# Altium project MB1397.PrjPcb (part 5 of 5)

## Sheet USB-TYPEC_CON.SchDoc: USB-TYPEC_CON
size A4; Date: Not used; ApprovedBy: Not used; CheckedBy: Not used; Author: Not used; CompanyName: STMicroelectronics; DrawnBy: Not used; Engineer: Not used; Organization: Not used; Address1: Not used; Address2: Not used; Address3: Not used; Address4: Not used; DocumentNumber: Not used; Revision: Not used; SheetNumber: 6; SheetTotal: 22
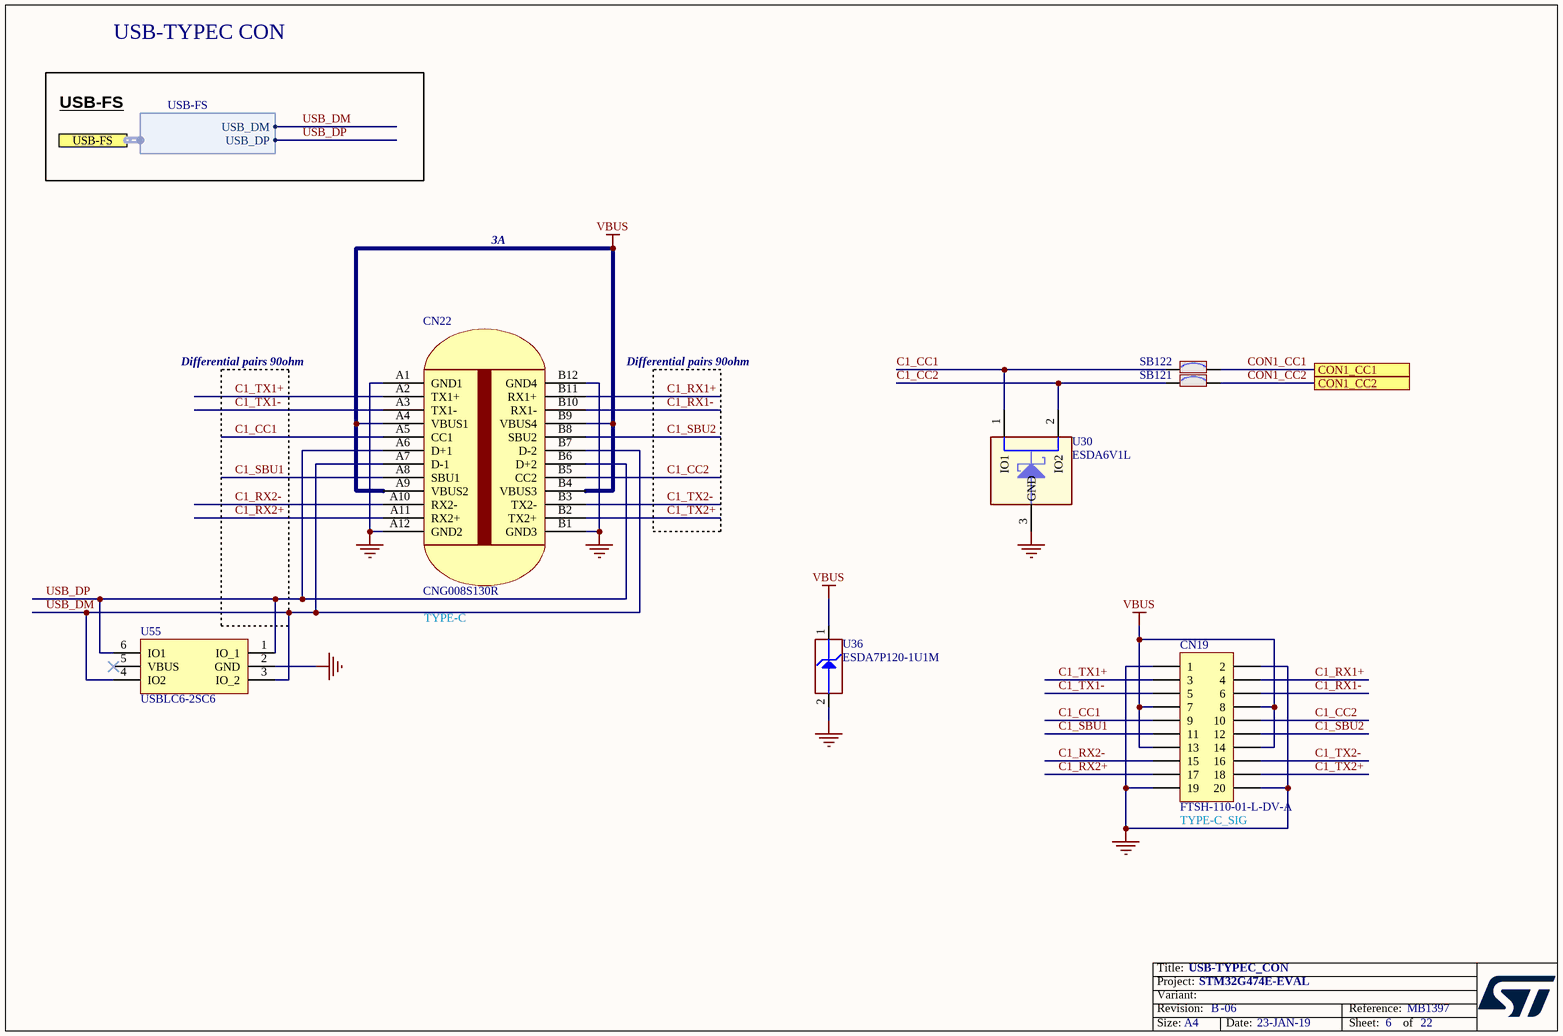
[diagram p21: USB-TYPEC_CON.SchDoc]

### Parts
CN19  value FTSH-110-01-L-DV-A  [CON_SAMTEC_FTSH-110-01-L-DV-A]  (hidden comment: Header 10x2)
CN22  value CNG008S130R  [CON_USB-TYPEC_LITKCONN-TECHNOLOGY_CNG008S130R]  (hidden comment: USB Type-C)
SB121  SB_ON  [SOLDER-BRIDGE_R0603-0R]  (value not drawn)
SB122  SB_ON  [SOLDER-BRIDGE_R0603-0R]  (value not drawn)
U30  value ESDA6V1L  [ESD_SOT23]  (hidden comment: ESDAxxL)
U36  value ESDA7P120-1U1M  [ESD_QFN1610_2N_1K_2A]  (hidden comment: ESD-TRANSIL)
U55  USBLC6-2SC6  [ESD_SOT23-6L]

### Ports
CON1_CC1, CON1_CC2, USB-FS (harness USB-FS)

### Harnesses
USB-FS: USB_DM, USB_DP

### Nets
GND: CN19.1 CN19.2 CN19.19 CN19.20 CN22.A1(GND1) CN22.A12(GND2) CN22.B1(GND3) CN22.B12(GND4) U30.3(GND) U36.2(GND) U55.2(GND)
VBUS: CN19.7 CN19.8 CN19.13 CN19.14 CN22.A4(VBUS1) CN22.A9(VBUS2) CN22.B4(VBUS3) CN22.B9(VBUS4) U36.1(IO1)
C1_CC1: CN19.9 CN22.A5(CC1) SB122.1 U30.1(IO1)
C1_CC2: CN19.10 CN22.B5(CC2) SB121.1 U30.2(IO2)
C1_RX1+: CN19.4 CN22.B11(RX1+)
C1_RX1-: CN19.6 CN22.B10(RX1-)
C1_RX2+: CN19.17 CN22.A11(RX2+)
C1_RX2-: CN19.15 CN22.A10(RX2-)
C1_SBU1: CN19.11 CN22.A8(SBU1)
C1_SBU2: CN19.12 CN22.B8(SBU2)
C1_TX1+: CN19.3 CN22.A2(TX1+)
C1_TX1-: CN19.5 CN22.A3(TX1-)
C1_TX2+: CN19.18 CN22.B2(TX2+)
C1_TX2-: CN19.16 CN22.B3(TX2-)
CON1_CC1: SB122.2 ; port CON1_CC1
CON1_CC2: SB121.2 ; port CON1_CC2
USB_DM: CN22.A7(D-1) CN22.B7(D-2) U55.3(IO_2) U55.4(IO2) ; port USB-FS.USB_DM
USB_DP: CN22.A6(D+1) CN22.B6(D+2) U55.1(IO_1) U55.6(IO1) ; port USB-FS.USB_DP

Not connected (* = marked no-connect by the designer): U55 5(VBUS)*

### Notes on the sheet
- USB-TYPEC CON
- USB-FS
- 3A
- Differential pairs 90ohm
- TYPE-C
- (near CN19) TYPE-C_SIG

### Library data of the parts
CN19 = MCD-01561: Header 10x2, 1.27mm, VR, CMS, Height 3.05mm with alignment pin; Part_Type: Connector; Manufacturer: SAMTEC; Provided_By: SUBCO; Initial_Board_Reference: MB1397; Path: ws/MCD_ApplicationBoards/Lists/MCDPARTSdatabase; Item Type: Item; Remark: new part FTSH-110-01-L-DV-A to replace MCD-00557 footprint
CN22 = MCD-00678: USB Type C certified Connector SMT Mid-mount; Manufacturer: LITKCON TECHNOLOGY; Provided_By: SUBCO; Initial_Board_Reference: MB1272; Path: ws/MCD_ApplicationBoards/Lists/MCDPARTSdatabase; Item Type: Item
SB121 SB122 = MCD-00071: Solder Bridge ON; Part_Type: Mechanical; Manufacturer_Part_Number: RC0603JR-070RL; Manufacturer: YAGEO; Provided_By: SUBCO; Initial_Board_Reference: MB1274; Path: ws/MCD_ApplicationBoards/Lists/MCDPARTSdatabase; Item Type: Item
U30 = MCD-00255: Dual Transil array ESD protection; Part_Type: Diode; Manufacturer: STMICROELECTRONICS; BMS_Part_Number: 9179033; Provided_By: SUBCO with ST control; Initial_Board_Reference: MB1311; Path: ws/MCD_ApplicationBoards/Lists/MCDPARTSdatabase; Item Type: Item
U36 = MCD-01026: High power transient voltage suppressor; Part_Type: Diode; Manufacturer: STMICROELECTRONICS; BMS_Part_Number: 9179046; Provided_By: SUBCO with ST control; Initial_Board_Reference: MB1378; Remark: Footprint moved fromROU lib: DFN105P160X60-2N to global-lib: ESD_QFN1610_2N_1K_2A; Path: ws/MCD_ApplicationBoards/Lists/MCDPARTSdatabase; Item Type: Item
U55 = MCD-00163: Very low capacitance ESD protection; Part_Type: IC; Manufacturer: STMICROELECTRONICS; BMS_Part_Number: 9151075; Provided_By: SUBCO with ST control; Initial_Board_Reference: MB1263; Path: ws/MCD_ApplicationBoards/Lists/MCDPARTSdatabase; Item Type: Item

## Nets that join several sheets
1V8: Audio (6 pins), Power_Board (SB42.2 TP4.1)
3V3: Audio (5 pins), LCD&SDcard (12 pins), MotorControl (10 pins), STM32_microcontroller_power (JP6.3 JP11.1), Power_Board (5 pins), Analog_Interfaces (R111.2), Peripherals (LD1.1 LD2.1 LD3.1 LD4.1), RS232&RS485 (7 pins)
5V: FDCAN (C44.1 C53.1 U10.3 U15.3), LCD&SDcard (SB46.1), MotorControl (CN2.25 CN4.25), SmartCard (C152.1 C153.2 U42.6), Power_Board (11 pins), Analog_Interfaces (C159.2 Q4.3 R318.2 U4.8), Multi-Function_Expander (R241.2 T8.4), Peripherals (SB1.2 SB34.2), STLink_V3E_SWD (R277.2), ExtensionConnector (CN5.60 CN6.60)
5V_D: Power_Board (JP12.5), STLink_V3E_SWD (D4.1), ExtensionConnector (CN5.49 CN6.49)
5V_EXT: Power_Board (8 pins), STLink_V3E_SWD (D3.1), USB_PD (5 pins)
5V_STLK: Power_Board (JP12.1), STLink_V3E_SWD (SB41.2)
5V_USB_CHGR: Power_Board (JP12.9), STLink_V3E_SWD (8 pins)
5V_USB_PD: Power_Board (JP12.3), STLink_V3E_SWD (D5.1), USB_PD (D8.2 D9.2)
AGND: STM32_microcontroller_power (10 pins), Analog_Interfaces (35 pins)
GND: FMC_Memory (7 pins), Audio (33 pins), QSPI_Memory (C51.1 C184.1 U12.10 U54.10), FDCAN (10 pins), LCD&SDcard (23 pins), MotorControl (49 pins), SmartCard (15 pins), STM32_microcontroller_power (33 pins), Power_Board (31 pins), HW_Mechanical_Parts (H1.1 H2.1 H5.1 H6.1), Analog_Interfaces (5 pins), Multi-Function_Expander (26 pins), Peripherals (17 pins), STLink_V3E_SWD (97 pins), ExtensionConnector (7 pins), USB_PD (10 pins), Debug_connector (26 pins), RS232&RS485 (14 pins), USB-TYPEC_CON (11 pins)
VBUS: USB_PD (10 pins), USB-TYPEC_CON (9 pins)
VDD: STM32_microcontroller_IOs (R73.2 R80.2), FMC_Memory (7 pins), Audio (5 pins), QSPI_Memory (6 pins), FDCAN (C40.1 C52.1 U10.5 U15.5), LCD&SDcard (8 pins), SmartCard (8 pins), STM32_microcontroller_power (JP7.1 JP11.2 SW7.2), Analog_Interfaces (C50.1 R158.2 R179.2 RV2.1), Multi-Function_Expander (11 pins), Peripherals (6 pins), STLink_V3E_SWD (CN16.3 R282.2), ExtensionConnector (CN5.48 CN6.48), Debug_connector (9 pins), RS232&RS485 (5 pins)
VDD_ADJ: STM32_microcontroller_power (JP11.3), Power_Board (SB48.2)
VDD_MCU: STM32_microcontroller_power (18 pins), Multi-Function_Expander (JP13.2 SB43.2)
VREF_EXT: STM32_microcontroller_power (SB84.1), Analog_Interfaces (5 pins)
A0: STM32_microcontroller_IOs (R136.2), FMC_Memory (U11.A3), ExtensionConnector (CN6.51)
A1: STM32_microcontroller_IOs (R138.2), FMC_Memory (U11.A4), ExtensionConnector (CN6.54)
A2: STM32_microcontroller_IOs (R132.2), FMC_Memory (U11.A5), ExtensionConnector (CN6.46)
A3: STM32_microcontroller_IOs (R139.2), FMC_Memory (U11.B3), ExtensionConnector (CN6.58)
A4: STM32_microcontroller_IOs (R140.2), FMC_Memory (U11.B4), ExtensionConnector (CN6.57)
A5: STM32_microcontroller_IOs (R137.2), FMC_Memory (U11.C3), ExtensionConnector (CN6.53)
A6: STM32_microcontroller_IOs (R93.2), FMC_Memory (U11.C4), ExtensionConnector (CN6.30)
A7: STM32_microcontroller_IOs (R89.2), FMC_Memory (U11.D4), ExtensionConnector (CN6.29)
A8: STM32_microcontroller_IOs (R88.2), FMC_Memory (U11.H2), ExtensionConnector (CN6.28)
A9: STM32_microcontroller_IOs (R87.2), FMC_Memory (U11.H3), ExtensionConnector (CN6.26)
A10: STM32_microcontroller_IOs (R48.2), FMC_Memory (U11.H4), ExtensionConnector (CN5.22)
A11: STM32_microcontroller_IOs (R28.2), FMC_Memory (U11.H5), ExtensionConnector (CN5.21)
A12: STM32_microcontroller_IOs (R50.2), FMC_Memory (U11.G3), ExtensionConnector (CN5.18)
A13: STM32_microcontroller_IOs (R27.2), FMC_Memory (U11.G4), ExtensionConnector (CN5.19)
A14: STM32_microcontroller_IOs (R53.2), FMC_Memory (U11.F3), ExtensionConnector (CN5.17)
A15: STM32_microcontroller_IOs (R68.2), FMC_Memory (U11.F4), ExtensionConnector (CN5.16)
A16: STM32_microcontroller_IOs (R39.2), FMC_Memory (U11.E4), ExtensionConnector (CN6.7)
A17: STM32_microcontroller_IOs (R42.2), FMC_Memory (U11.D3), ExtensionConnector (CN6.6)
A18: STM32_microcontroller_IOs (R41.2), FMC_Memory (U11.H1), ExtensionConnector (CN6.5)
A19: STM32_microcontroller_IOs (R146.1), FMC_Memory (R156.2 U11.G2), ExtensionConnector (CN5.54)
A20: STM32_microcontroller_IOs (R143.1), FMC_Memory (R162.2 U11.H6), ExtensionConnector (CN5.56)
ADC_OUTN: STM32_microcontroller_IOs (SB27.1), Analog_Interfaces (C35.1 R152.2)
Audio_INT: STM32_microcontroller_IOs (R43.2), Audio (U35.G3)
BK_Drive: STM32_microcontroller_IOs (R26.1), Peripherals (R175.1)
BOOT0: STM32_microcontroller_IOs (R123.1), STM32_microcontroller_power (JP8.2 R182.1)
CON1_CC1: STM32_microcontroller_IOs (SB21.2), USB_PD (JP15.3), USB-TYPEC_CON (SB122.2)
CON1_CC2: STM32_microcontroller_IOs (SB96.2), USB_PD (JP14.3), USB-TYPEC_CON (SB121.2)
D0: STM32_microcontroller_IOs (R29.2), FMC_Memory (U11.B6), ExtensionConnector (CN6.4)
D1: STM32_microcontroller_IOs (R40.2), FMC_Memory (U11.C5), ExtensionConnector (CN6.3)
D2: STM32_microcontroller_IOs (R83.2), FMC_Memory (U11.C6), ExtensionConnector (CN5.27)
D3: STM32_microcontroller_IOs (R85.2), FMC_Memory (U11.D5), ExtensionConnector (CN5.28)
D4: STM32_microcontroller_IOs (R84.1), FMC_Memory (U11.E5), ExtensionConnector (CN6.27)
D5: STM32_microcontroller_IOs (R82.1), FMC_Memory (U11.F5), ExtensionConnector (CN6.25)
D6: STM32_microcontroller_IOs (R79.1), FMC_Memory (U11.F6), ExtensionConnector (CN6.24)
D7: STM32_microcontroller_IOs (R75.1), FMC_Memory (U11.G6), ExtensionConnector (CN6.23)
D8: STM32_microcontroller_IOs (R71.1), FMC_Memory (U11.B1), ExtensionConnector (CN6.22)
D9: STM32_microcontroller_IOs (R69.1), FMC_Memory (U11.C1), ExtensionConnector (CN6.21)
D10: STM32_microcontroller_IOs (R63.1), FMC_Memory (U11.C2), ExtensionConnector (CN6.20)
D11: STM32_microcontroller_IOs (R62.1), FMC_Memory (U11.D2), ExtensionConnector (CN6.19)
D12: STM32_microcontroller_IOs (R60.1), FMC_Memory (U11.E2), ExtensionConnector (CN6.18)
D13: STM32_microcontroller_IOs (R34.2), FMC_Memory (U11.F2), ExtensionConnector (CN6.12)
D14: STM32_microcontroller_IOs (R37.2), FMC_Memory (U11.F1), ExtensionConnector (CN6.9)
D15: STM32_microcontroller_IOs (R38.2), FMC_Memory (U11.G1), ExtensionConnector (CN6.8)
DAC: STM32_microcontroller_IOs (SB25.1), Analog_Interfaces (R153.2)
DISCHARGE: STM32_microcontroller_IOs (SB18.2), USB_PD (SB44.1)
FDCAN1_RX: STM32_microcontroller_IOs (JP1.2), FDCAN (U15.4)
FDCAN1_TX: STM32_microcontroller_IOs (R127.2), FDCAN (U15.1)
FDCAN2_RX: STM32_microcontroller_IOs (R112.2), FDCAN (U10.4)
FDCAN2_TX: STM32_microcontroller_IOs (SB5.2), FDCAN (U10.1)
FMC_NBL0: STM32_microcontroller_IOs (R148.1), FMC_Memory (U11.A1), ExtensionConnector (CN5.55)
FMC_NBL1: STM32_microcontroller_IOs (R149.1), FMC_Memory (U11.B2), ExtensionConnector (CN5.53)
FMC_NE1: STM32_microcontroller_IOs (R101.2), FMC_Memory (R171.1 U11.B5), ExtensionConnector (CN5.40)
FMC_NOE: STM32_microcontroller_IOs (R94.2), FMC_Memory (U11.A2), ExtensionConnector (CN5.33)
FMC_NWE: STM32_microcontroller_IOs (R97.2), FMC_Memory (U11.G5), ExtensionConnector (CN5.38)
I2C3_SCL: STM32_microcontroller_IOs (R73.1 R74.2), Multi-Function_Expander (R243.1), Peripherals (CN1.3 R17.1 U1.1 U1.6)
I2C3_SDA: STM32_microcontroller_IOs (R78.2 R80.1), Multi-Function_Expander (R239.1), Peripherals (CN1.1 R13.1 U1.3 U1.4)
I2C3_SMBA: STM32_microcontroller_IOs (R70.2), Peripherals (R15.1 R16.1)
JTCK-SWCLK: STM32_microcontroller_IOs (R47.1), STLink_V3E_SWD (CN29.1 R206.2 U40.M11), Debug_connector (R193.2)
JTDI: STM32_microcontroller_IOs (R54.1), STLink_V3E_SWD (R199.2), Debug_connector (R185.2)
JTDO-SWO: STM32_microcontroller_IOs (R107.2), STLink_V3E_SWD (R204.2 U40.D12), Debug_connector (R209.2)
JTMS-SWDIO: STM32_microcontroller_IOs (R44.1), STLink_V3E_SWD (CN29.2 R208.2 R285.2 U40.L2), Debug_connector (R188.2)
JTRST: STM32_microcontroller_IOs (R109.1), Debug_connector (R205.2)
LCD_CS: STM32_microcontroller_IOs (R49.1), LCD&SDcard (R216.1)
LED1: STM32_microcontroller_IOs (R81.2), Peripherals (R297.2)
LED3: STM32_microcontroller_IOs (R96.2), Peripherals (R299.2)
MC1_Ain: STM32_microcontroller_IOs (SB113.1), MotorControl (R64.2)
MC1_Bin: STM32_microcontroller_IOs (SB114.1), MotorControl (R55.2)
MC1_BusVoltage: STM32_microcontroller_IOs (SB115.1), MotorControl (C4.1 R3.2)
MC1_Cin: STM32_microcontroller_IOs (SB99.1), MotorControl (R52.2)
MC1_DissipativeBrake: STM32_microcontroller_IOs (SB97.1), MotorControl (CN2.23)
MC1_EnA: STM32_microcontroller_IOs (SB98.1), MotorControl (C3.2 CN2.31 SB2.1)
MC1_EnB: STM32_microcontroller_IOs (SB89.1), MotorControl (C9.2 CN2.33)
MC1_EnIndex: STM32_microcontroller_IOs (SB62.1 SB92.1), MotorControl (C11.2 CN2.34)
MC1_ICL_SHUTOUT: STM32_microcontroller_IOs (SB109.1), MotorControl (CN2.21)
MC1_MC2_PFC_Ind: STM32_microcontroller_IOs (SB55.1), MotorControl (C7.2 C29.2 R5.2 R113.2)
MC1_MC2_PFC_SD: STM32_microcontroller_IOs (SB17.1), MotorControl (R10.2 R128.2)
MC1_MC2_PFC_Vac: STM32_microcontroller_IOs (SB56.1), MotorControl (C10.2 C34.2 R12.2 R155.2)
MC1_MC2_PFCpwm: STM32_microcontroller_IOs (SB118.1), MotorControl (R11.1 R151.1)
MC1_MC2_PFCsync: STM32_microcontroller_IOs (SB103.1), MotorControl (R8.1 R126.1)
MC1_PWM_1H: STM32_microcontroller_IOs (SB78.1), MotorControl (CN2.3)
MC1_PWM_1L: STM32_microcontroller_IOs (SB79.1), MotorControl (CN2.5)
MC1_PWM_2H: STM32_microcontroller_IOs (SB76.1), MotorControl (CN2.7)
MC1_PWM_2L: STM32_microcontroller_IOs (SB77.1), MotorControl (CN2.9)
MC1_PWM_3H: STM32_microcontroller_IOs (SB73.1), MotorControl (CN2.11)
MC1_PWM_3L: STM32_microcontroller_IOs (SB74.1), MotorControl (CN2.13)
MC1_STOP: STM32_microcontroller_IOs (SB69.1), MotorControl (C1.2 CN2.1 R9.1)
MC1_Temp: STM32_microcontroller_IOs (SB100.1), MotorControl (C5.2 R7.2)
MC2_Ain: STM32_microcontroller_IOs (SB60.1), MotorControl (R103.2)
MC2_Bin: STM32_microcontroller_IOs (SB59.1), MotorControl (R99.2)
MC2_BusVoltage: STM32_microcontroller_IOs (SB72.1), MotorControl (C22.1 R77.2)
MC2_Cin: STM32_microcontroller_IOs (SB57.1), MotorControl (R119.2)
MC2_DissipativeBrake: STM32_microcontroller_IOs (SB112.1), MotorControl (CN4.23)
MC2_EnA: STM32_microcontroller_IOs (SB52.1), MotorControl (C37.2 CN4.31 SB32.1)
MC2_EnB: STM32_microcontroller_IOs (SB108.1), MotorControl (C42.2 CN4.33)
MC2_EnIndex: STM32_microcontroller_IOs (SB58.1 SB106.1), MotorControl (C39.2 CN4.34)
MC2_ICL_SHUTOUT: STM32_microcontroller_IOs (SB61.1), MotorControl (CN4.21)
MC2_PWM_1H: STM32_microcontroller_IOs (SB49.1), MotorControl (CN4.3)
MC2_PWM_1L: STM32_microcontroller_IOs (SB64.1), MotorControl (CN4.5)
MC2_PWM_2H: STM32_microcontroller_IOs (SB50.1), MotorControl (CN4.7)
MC2_PWM_2L: STM32_microcontroller_IOs (SB68.1), MotorControl (CN4.9)
MC2_PWM_3H: STM32_microcontroller_IOs (SB51.1), MotorControl (CN4.11)
MC2_PWM_3L: STM32_microcontroller_IOs (SB66.1), MotorControl (CN4.13)
MC2_STOP: STM32_microcontroller_IOs (SB23.1), MotorControl (R21.1)
MC2_Temp: STM32_microcontroller_IOs (SB83.1), MotorControl (C31.2 R120.2)
MC_DAC_OUT1: STM32_microcontroller_IOs (SB93.1), MotorControl (SW3.3 SW3.6 SW4.2)
MC_DAC_OUT2: STM32_microcontroller_IOs (SB24.1), MotorControl (CN32.1)
MFX_JOY_DOWN: Multi-Function_Expander (U32.19), Peripherals (B1.3 U49.4)
MFX_JOY_LEFT: Multi-Function_Expander (U32.20), Peripherals (B1.1 U49.6)
MFX_JOY_RIGHT: Multi-Function_Expander (U32.39), Peripherals (B1.6 U49.3)
MFX_JOY_SEL: Multi-Function_Expander (U32.18), Peripherals (B1.2 U49.5)
MFX_JOY_UP: Multi-Function_Expander (U32.40), Peripherals (B1.4 U49.1)
MFX_SmartCard_1V8: SmartCard (R275.1 R276.2 U42.18), Multi-Function_Expander (U32.29)
MFX_SmartCard_3/5V: SmartCard (U42.3), Multi-Function_Expander (U32.30)
MFX_SmartCard_CMDVCC: SmartCard (U42.19), Multi-Function_Expander (U32.32)
MFX_SmartCard_OFF: SmartCard (U42.23), Multi-Function_Expander (U32.31)
MFX_SmartCard_RST: SmartCard (U42.20), Multi-Function_Expander (U32.33)
NetC49_2: STM32_microcontroller_IOs (SB10.2), Peripherals (C49.2 R172.2)
NetC171_2: STM32_microcontroller_IOs (SB116.2), Analog_Interfaces (C171.2 R310.2)
NetD2_1: STM32_microcontroller_power (D2.1), RS232&RS485 (U17.20)
NetJP18_2: STM32_microcontroller_power (JP18.2), RS232&RS485 (U17.16)
NetR312_1: STM32_microcontroller_power (R312.1), STLink_V3E_SWD (U40.F15)
NRST: STM32_microcontroller_IOs (U6.21), STM32_microcontroller_power (5 pins), Multi-Function_Expander (D7.2), STLink_V3E_SWD (R196.2 U40.P3), ExtensionConnector (R309.2)
OPAMP1_INN: STM32_microcontroller_IOs (SB105.1), MotorControl (C20.1 R65.2 R67.2)
OPAMP1_INP: STM32_microcontroller_IOs (SB95.1), MotorControl (R61.2)
OPAMP1_OUT: STM32_microcontroller_IOs (SB117.1), MotorControl (C20.2 R67.1)
OPAMP2_IN1P: STM32_microcontroller_IOs (SB101.1), MotorControl (R31.2)
OPAMP2_IN2P: STM32_microcontroller_IOs (SB70.1), MotorControl (C15.1 R24.2 R25.1)
OPAMP2_INN: STM32_microcontroller_IOs (SB20.1), MotorControl (C19.1 R56.2 R57.2)
OPAMP2_OUT: STM32_microcontroller_IOs (SB104.1), MotorControl (C19.2 R57.1)
OPAMP3_INN: STM32_microcontroller_IOs (SB80.1), MotorControl (C27.1 R105.2 R106.2)
OPAMP3_INP: STM32_microcontroller_IOs (SB94.1), MotorControl (R125.2)
OPAMP3_OUT: STM32_microcontroller_IOs (SB91.1), MotorControl (C27.2 R105.1)
OPAMP4/COMP6_INP: STM32_microcontroller_IOs (SB8.2), Analog_Interfaces (R164.1)
OPAMP4_IN1P: STM32_microcontroller_IOs (SB67.1), MotorControl (C14.1 R20.1 R22.2)
OPAMP4_IN2P: STM32_microcontroller_IOs (SB63.1), MotorControl (R91.2)
OPAMP4_INN: STM32_microcontroller_IOs (SB71.1), MotorControl (C17.1 R32.2 R33.2)
OPAMP4_OUT: STM32_microcontroller_IOs (SB65.1), MotorControl (C17.2 R33.1)
OPAMP4_VOUT: STM32_microcontroller_IOs (SB7.2), Analog_Interfaces (RV1.2 RV1.3 TP2.1)
PA0: STM32_microcontroller_IOs (SB26.2 SB98.2 SB116.1 U6.27), ExtensionConnector (CN6.45)
PA1: STM32_microcontroller_IOs (SB27.2 SB95.2 U6.28), ExtensionConnector (CN6.44)
PA4: STM32_microcontroller_IOs (SB25.2 SB93.2 U6.33), ExtensionConnector (CN6.41)
PA5: STM32_microcontroller_IOs (SB24.2 U6.34), ExtensionConnector (CN6.40)
PA8: STM32_microcontroller_IOs (R30.2 U6.89), ExtensionConnector (CN5.2)
PA9: STM32_microcontroller_IOs (SB4.2 SB54.2 U6.90), ExtensionConnector (CN5.8)
PA10: STM32_microcontroller_IOs (SB3.2 SB53.2 U6.91), ExtensionConnector (CN5.4)
PA11: STM32_microcontroller_IOs (R46.2 U6.92), ExtensionConnector (CN5.3)
PA12: STM32_microcontroller_IOs (R45.2 U6.93), ExtensionConnector (CN5.5)
PA13: STM32_microcontroller_IOs (R44.2 U6.96), ExtensionConnector (CN5.6)
PA14: STM32_microcontroller_IOs (R47.2 U6.98), ExtensionConnector (CN5.9)
PA15: STM32_microcontroller_IOs (R54.2 SB62.2 U6.99), ExtensionConnector (CN5.12)
PB2: STM32_microcontroller_IOs (SB18.1 SB80.2 U6.41), ExtensionConnector (CN6.32)
PB3: STM32_microcontroller_IOs (R107.1 U6.118), ExtensionConnector (CN5.41)
PB4: STM32_microcontroller_IOs (R109.2 SB96.1 U6.119), ExtensionConnector (CN5.42)
PB5: STM32_microcontroller_IOs (R112.1 U6.120), ExtensionConnector (CN5.43)
PB6: STM32_microcontroller_IOs (SB21.1 U6.121), ExtensionConnector (CN5.44)
PB7: STM32_microcontroller_IOs (SB23.2 U6.122), ExtensionConnector (CN5.47)
PB8: STM32_microcontroller_IOs (JP1.1 R123.2 U6.123), ExtensionConnector (CN5.52)
PB9: STM32_microcontroller_IOs (R127.1 U6.124), ExtensionConnector (CN5.51)
PB10: STM32_microcontroller_IOs (SB11.1 SB71.2 U6.62), ExtensionConnector (CN6.17)
PB11: STM32_microcontroller_IOs (SB8.1 SB10.1 SB67.2 U6.65), ExtensionConnector (CN6.15)
PB12: STM32_microcontroller_IOs (SB7.1 SB65.2 U6.66), ExtensionConnector (CN6.16)
PB13: STM32_microcontroller_IOs (SB5.1 SB63.2 U6.67), ExtensionConnector (CN6.13)
PB14: STM32_microcontroller_IOs (R35.1 U6.68), ExtensionConnector (CN6.11)
PB15: STM32_microcontroller_IOs (R36.1 U6.69), ExtensionConnector (CN6.14)
PC0: STM32_microcontroller_IOs (SB29.2 SB99.2 U6.22), ExtensionConnector (CN5.46)
PC5: STM32_microcontroller_IOs (SB20.2 U6.38), ExtensionConnector (CN6.34)
PC6: STM32_microcontroller_IOs (SB9.2 SB49.2 U6.80), ExtensionConnector (CN6.2)
PC7: STM32_microcontroller_IOs (SB6.2 SB50.2 U6.81), ExtensionConnector (CN6.1)
PC8: STM32_microcontroller_IOs (R26.2 SB51.2 U6.87), ExtensionConnector (CN5.1)
PC9: STM32_microcontroller_IOs (R49.2 U6.88), ExtensionConnector (CN5.11)
PC10: STM32_microcontroller_IOs (SB12.2 SB64.2 U6.100), ExtensionConnector (CN5.13)
PC11: STM32_microcontroller_IOs (SB13.2 SB68.2 U6.101), ExtensionConnector (CN5.15)
PC12: STM32_microcontroller_IOs (SB15.2 SB66.2 U6.102), ExtensionConnector (CN5.14)
PC13: STM32_microcontroller_IOs (R141.2 U6.7), ExtensionConnector (CN5.57)
PC14: STM32_microcontroller_IOs (U6.8), STM32_microcontroller_power (R315.2), ExtensionConnector (SB88.1)
PC15: STM32_microcontroller_IOs (U6.9), STM32_microcontroller_power (R314.2), ExtensionConnector (SB87.2)
PD2: STM32_microcontroller_IOs (SB17.2 SB123.1 U6.112), ExtensionConnector (CN5.29)
PD6: STM32_microcontroller_IOs (R98.1 U6.116), ExtensionConnector (CN5.37)
PD_DBCC1: STM32_microcontroller_IOs (SB54.1), USB_PD (JP15.2)
PD_DBCC2: STM32_microcontroller_IOs (SB53.1), USB_PD (JP14.2)
PE2: STM32_microcontroller_IOs (R147.2 SB103.2 SB111.2 U6.1), ExtensionConnector (CN5.50)
PE5: STM32_microcontroller_IOs (SB28.2 SB97.2 U6.4), ExtensionConnector (CN5.45)
PE6: STM32_microcontroller_IOs (R142.2 U6.5), ExtensionConnector (CN5.58)
PF0: STM32_microcontroller_IOs (U6.19), STM32_microcontroller_power (C172.1 R312.2 R317.2), ExtensionConnector (SB82.1)
PF1: STM32_microcontroller_IOs (U6.20), STM32_microcontroller_power (R313.2), ExtensionConnector (SB81.2)
PF6: STM32_microcontroller_IOs (R43.1 SB52.2 U6.97), ExtensionConnector (CN5.7)
PF8: STM32_microcontroller_IOs (R135.1 SB106.2 U6.16), ExtensionConnector (CN6.56)
PF9: STM32_microcontroller_IOs (R134.1 U6.17), ExtensionConnector (CN6.55)
PF11: STM32_microcontroller_IOs (R96.1 U6.48), ExtensionConnector (CN6.31)
PG6: STM32_microcontroller_IOs (R70.1 U6.104), ExtensionConnector (CN5.24)
PG7: STM32_microcontroller_IOs (R74.1 U6.105), ExtensionConnector (CN5.23)
PG8: STM32_microcontroller_IOs (R78.1 U6.106), ExtensionConnector (CN5.25)
PG9: STM32_microcontroller_IOs (R81.1 U6.107), ExtensionConnector (CN5.26)
QSPI_BK1_IO0: STM32_microcontroller_IOs (R102.2), QSPI_Memory (R173.2), ExtensionConnector (CN6.33)
QSPI_BK1_IO1: STM32_microcontroller_IOs (R108.2), QSPI_Memory (R159.1), ExtensionConnector (CN6.35)
QSPI_BK1_IO2: STM32_microcontroller_IOs (R118.1), QSPI_Memory (R160.2), ExtensionConnector (CN6.37)
QSPI_BK1_IO3: STM32_microcontroller_IOs (R121.1), QSPI_Memory (R178.1), ExtensionConnector (CN6.38)
QSPI_BK1_NCS: STM32_microcontroller_IOs (R150.1), QSPI_Memory (R161.2 SB35.1 U12.7), ExtensionConnector (CN6.43)
QSPI_BK2_IO0: STM32_microcontroller_IOs (R130.1), QSPI_Memory (R170.2 R320.2), ExtensionConnector (CN6.52)
QSPI_BK2_IO1: STM32_microcontroller_IOs (R133.1), QSPI_Memory (R168.1 R321.1), ExtensionConnector (CN6.50)
QSPI_BK2_IO2: STM32_microcontroller_IOs (R131.1), QSPI_Memory (R167.2 R322.2), ExtensionConnector (CN6.47)
QSPI_BK2_IO3: STM32_microcontroller_IOs (R116.1), QSPI_Memory (R169.1 R319.1), ExtensionConnector (CN6.36)
QSPI_BK2_NCS: STM32_microcontroller_IOs (R90.2), QSPI_Memory (R166.2 SB120.1 U54.7), ExtensionConnector (CN5.34)
QSPI_CLK: STM32_microcontroller_IOs (R129.1), QSPI_Memory (SB36.2 SB119.2 U12.16), ExtensionConnector (CN6.42)
RS485_DIR: STM32_microcontroller_IOs (SB123.2), RS232&RS485 (R201.1 U23.3)
SAI_FS_A: STM32_microcontroller_IOs (SB107.1), Audio (U35.E3)
SAI_MCLK_A: STM32_microcontroller_IOs (SB111.1), Audio (U35.D3)
SAI_SCK_A: STM32_microcontroller_IOs (R30.1), Audio (U35.G1)
SAI_SD_A: STM32_microcontroller_IOs (R98.2), Audio (U35.E4)
SAI_SD_B: STM32_microcontroller_IOs (SB110.1), Audio (U35.F2)
SmartCard_CLK: STM32_microcontroller_IOs (SB15.1), SmartCard (U42.24)
SmartCard_IO: STM32_microcontroller_IOs (SB12.1), SmartCard (U42.26)
SOURCE_EN: STM32_microcontroller_IOs (SB13.1), USB_PD (R264.2 T10.3)
SPI2_MISO: STM32_microcontroller_IOs (R35.2), LCD&SDcard (5 pins)
SPI2_MOSI: STM32_microcontroller_IOs (R36.2), LCD&SDcard (U28.2)
SPI2_SCK: STM32_microcontroller_IOs (R134.2), LCD&SDcard (R218.1 U26.2)
TAMPER_KEY: STM32_microcontroller_IOs (R141.1), Peripherals (5 pins)
TRACECLK: STM32_microcontroller_IOs (R147.1), Debug_connector (CN17.12 U20.1)
TRACED0: STM32_microcontroller_IOs (R145.1), Debug_connector (CN17.14 R210.1 U24.5)
TRACED1: STM32_microcontroller_IOs (R144.1), Debug_connector (CN17.16 R207.1 U24.4)
TRACED2: STM32_microcontroller_IOs (SB28.1), Debug_connector (CN17.18 U24.3)
TRACED3: STM32_microcontroller_IOs (R142.1), Debug_connector (CN17.20 U24.1)
USART1_RX: STM32_microcontroller_IOs (SB3.1), RS232&RS485 (JP9.2)
USART1_TX: STM32_microcontroller_IOs (SB4.1), RS232&RS485 (SB40.1)
USB_DM: STM32_microcontroller_IOs (R46.1), USB-TYPEC_CON (CN22.A7 CN22.B7 U55.3 U55.4)
USB_DP: STM32_microcontroller_IOs (R45.1), USB-TYPEC_CON (CN22.A6 CN22.B6 U55.1 U55.6)
uSD_CS: STM32_microcontroller_IOs (R135.2), LCD&SDcard (CN28.2 R287.1 U46.4 U46.7)
VSENSE: STM32_microcontroller_IOs (SB29.1), USB_PD (C185.2 R244.1 R323.2)

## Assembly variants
G474E: not fitted C2 C3 C6 C8 C9 C10 C11 C17 C19 C20 C23 C24 C26 C27 C29 C31 C33 C34 C36 C37 C39 C42 C46 C172 CN7 CN8 CN15 CN18 CN27 CN29 CN30 L1 L8 L9 R32 R33 R56 R57 R65 R67 R105 R106 R113 R126 R128 R151 R155 R158 R167 R168 R169 R170 R183 R184 R186 R195 R197 R199 R200 R207 R210 R224 R225 R235 R240 R261 R275 R276 R286 R294 R312; alternate parts SB35 -> MCD-00072, SB8 -> MCD-00072, SB10 -> MCD-00071
G474EMC: not fitted C2 C3 C6 C8 C9 C10 C11 C23 C24 C26 C29 C31 C33 C34 C36 C37 C39 C42 C46 C172 CN7 CN8 CN15 CN18 CN27 CN29 CN30 L1 L8 L9 R26 R29 R34 R37 R38 R40 R41 R42 R43 R60 R62 R63 R69 R71 R75 R79 R82 R84 R94 R101 R102 R108 R113 R116 R118 R121 R126 R128 R129 R130 R131 R133 R135 R138 R143 R146 R150 R151 R155 R158 R167 R168 R169 R170 R183 R184 R186 R195 R197 R199 R200 R207 R210 R224 R225 R235 R240 R261 R275 R276 R286 R294 R312; alternate parts SB35 -> MCD-00072, SB69 -> MCD-00071, SB73 -> MCD-00071, SB74 -> MCD-00071, SB76 -> MCD-00071, SB78 -> MCD-00071, SB77 -> MCD-00071, SB79 -> MCD-00071, SB89 -> MCD-00071, SB92 -> MCD-00071, SB98 -> MCD-00071, SB26 -> MCD-00072, SB103 -> MCD-00071, SB118 -> MCD-00071, SB17 -> MCD-00071, SB110 -> MCD-00072, SB97 -> MCD-00071, SB109 -> MCD-00071, SB100 -> MCD-00071, SB115 -> MCD-00071, SB55 -> MCD-00071, SB56 -> MCD-00071, SB49 -> MCD-00071, SB64 -> MCD-00071, SB50 -> MCD-00071, SB68 -> MCD-00071, SB66 -> MCD-00071, SB51 -> MCD-00071, SB52 -> MCD-00071, SB108 -> MCD-00071, SB106 -> MCD-00071, SB112 -> MCD-00071, SB61 -> MCD-00071, SB72 -> MCD-00071, SB83 -> MCD-00071, SB93 -> MCD-00071, SB113 -> MCD-00071, SB114 -> MCD-00071, SB99 -> MCD-00071, SB57 -> MCD-00071, SB59 -> MCD-00071, SB60 -> MCD-00071, SB95 -> MCD-00071, SB105 -> MCD-00071, SB117 -> MCD-00071, SB101 -> MCD-00071, SB70 -> MCD-00071, SB67 -> MCD-00071, SB104 -> MCD-00071, SB63 -> MCD-00071, SB71 -> MCD-00071, SB65 -> MCD-00071, SB94 -> MCD-00071, SB91 -> MCD-00071, SB80 -> MCD-00071, SB12 -> MCD-00072, SB29 -> MCD-00072, SB27 -> MCD-00072, SB5 -> MCD-00072, SB7 -> MCD-00072, SB8 -> MCD-00072, SB11 -> MCD-00072, SB18 -> MCD-00072, SB9 -> MCD-00072, SB123 -> MCD-00072
G484E: not fitted C2 C3 C6 C8 C9 C10 C11 C17 C19 C20 C23 C24 C26 C27 C29 C31 C33 C34 C36 C37 C39 C42 C46 C172 CN7 CN8 CN15 CN18 CN27 CN29 CN30 L1 L8 L9 R32 R33 R56 R57 R65 R67 R105 R106 R113 R126 R128 R151 R155 R158 R167 R168 R169 R170 R183 R184 R186 R195 R197 R199 R200 R207 R210 R224 R225 R235 R240 R261 R275 R276 R286 R294 R312; alternate parts SB35 -> MCD-00072, SB8 -> MCD-00072, SB10 -> MCD-00071, U6 -> MCD-01708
